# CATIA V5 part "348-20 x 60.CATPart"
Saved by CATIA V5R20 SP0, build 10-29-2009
Part number: 348-20 x 60
Definition: NONE
Nomenclature: 348-20 x 60
Source: Unknown
Description: 348-20 x 60
Bounding box of the stored display mesh (mm): x 0 to 60, y -15 to 15, z -15 to 15
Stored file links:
  C:\Users\Utente\Desktop\IO LAVORO\3D X SITO CF\X SITO\3D files 348\348-20 x 60.CATPart
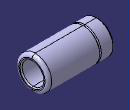
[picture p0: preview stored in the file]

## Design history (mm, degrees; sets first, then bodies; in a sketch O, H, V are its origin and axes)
Body1 "348-20 x 60" (main body)
  Solid1: solid without history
